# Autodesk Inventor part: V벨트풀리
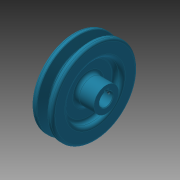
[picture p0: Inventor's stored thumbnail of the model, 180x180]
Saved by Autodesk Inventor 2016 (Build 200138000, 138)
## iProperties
Created: 2015-11
Part Number: V벨트풀리
Material: 강철, 탄소
Document SubType Name: Modeling
Designer: mduedu
Density: 1 g/cm^3
Appearance: 터키옥색
Author: mduedu
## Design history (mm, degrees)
sketch "스케치1"
  geometry: L1 (-9.5, 0)-(9.5, 0); L2 (0, 0)-(0, 37.7); L3 (-4.825, 37.7)-(-9.5, 37.7); L4 (-9.5, 37.7)-(-9.5, 0); L5 (0, 28.7)-(-2.074, 28.7); L6 (-2.074, 28.7)-(-4.825, 37.7); L7 (4.825, 37.7)-(9.5, 37.7); L8 (9.5, 37.7)-(9.5, 0); L9 (0, 28.7)-(2.074, 28.7); L10 (2.074, 28.7)-(4.825, 37.7); L11 (-9.5, 35)-(9.5, 35); 3 further points
  constraints: 22 end point, 7 point on line, 4 perpendicular, 3 symmetric about line, 1 coincident, 1 horizontal, 1 horizontal alignment, 1 midpoint, 1 vertical
  dimensions: "d0" = 19 distance of L1.start L1.end; "d2" = 75.4 diameter of L2.end L1 (derived); "d3" = 34 deg angle of L10 L6; "d4" = 6.3 distance between parallel lines of L11 L9; "d5" = 2.7 distance between parallel lines of L7 L11; "d6" = 8 distance of point (4, 35) point (-4, 35); "d7" = 70 diameter of L11 L1
revolve "회전1" sketch "스케치1" stored, may be unused: angle "d8" = 90 deg
sketch "스케치2"
  geometry: C1 r 24 at (0, 0); C2 r 11 at (0, 0); 1 further point
  constraints: 2 centre point, 2 coincident
  dimensions: "d9" = 48 diameter of C1; "d10" = 22 diameter of C2
extrude "돌출1" cut sketch "스케치2" distance "d11" = 6; taper "d12" = 0 deg
extrude "돌출3" join sketch "스케치2" distance "d37" = 10; taper "d38" = 0 deg
fillet "모깎기1" dims "d13" = 3
fillet "모깎기2" dims "d14" = 3
fillet "모깎기3" dims "d15" = 1, "d16" = 0.5, "d17" = 2
hole "구멍1" diameter "d20" = 12; stored, may be unused: countersink angle "d24" = 90 deg, drill point angle "d26" = 118 deg; dims "d21" = 6, "d22" = 4, "d23" = 2, "d25" = 8, "d39" = 10, "d40" = 10
sketch "스케치3"
  geometry: L1 (-2, 0)-(2, 0); L2 (2, 0)-(2, 7.8); L3 (2, 7.8)-(-2, 7.8); L4 (-2, 7.8)-(-2, 0); 2 further points
  constraints: 8 end point, 2 parallel, 1 coincident, 1 horizontal, 1 midpoint, 1 perpendicular
  dimensions: "d27" = 4 distance of L2.end L3.end; "d29" = 7.8 distance of L3.end L1.start
extrude "돌출2" cut sketch "스케치3" stored distance "d30" = 6; taper "d31" = 0 deg
chamfer "모따기1" distance "d32" = 0.5; stored, may be unused: second distance "d33" = 2, angle "d34" = 45 deg
node "작업 평면1"
sketch "스케치4"
  geometry: L1 (-19, 11)-(-19, -11) reference; 2 further points
  constraints: 1 horizontal alignment
  dimensions: "d41" = 25 distance from line of point (6, 0) L1
hole "구멍2" sketch "스케치4" at (6, 0) diameter "d42" = 2.459; stored, may be unused: countersink angle "d46" = 90 deg, drill point angle "d48" = 118 deg; dims "d43" = 6, "d44" = 4, "d45" = 2, "d47" = 8
node "솔리드1"
mirror "대칭1"
